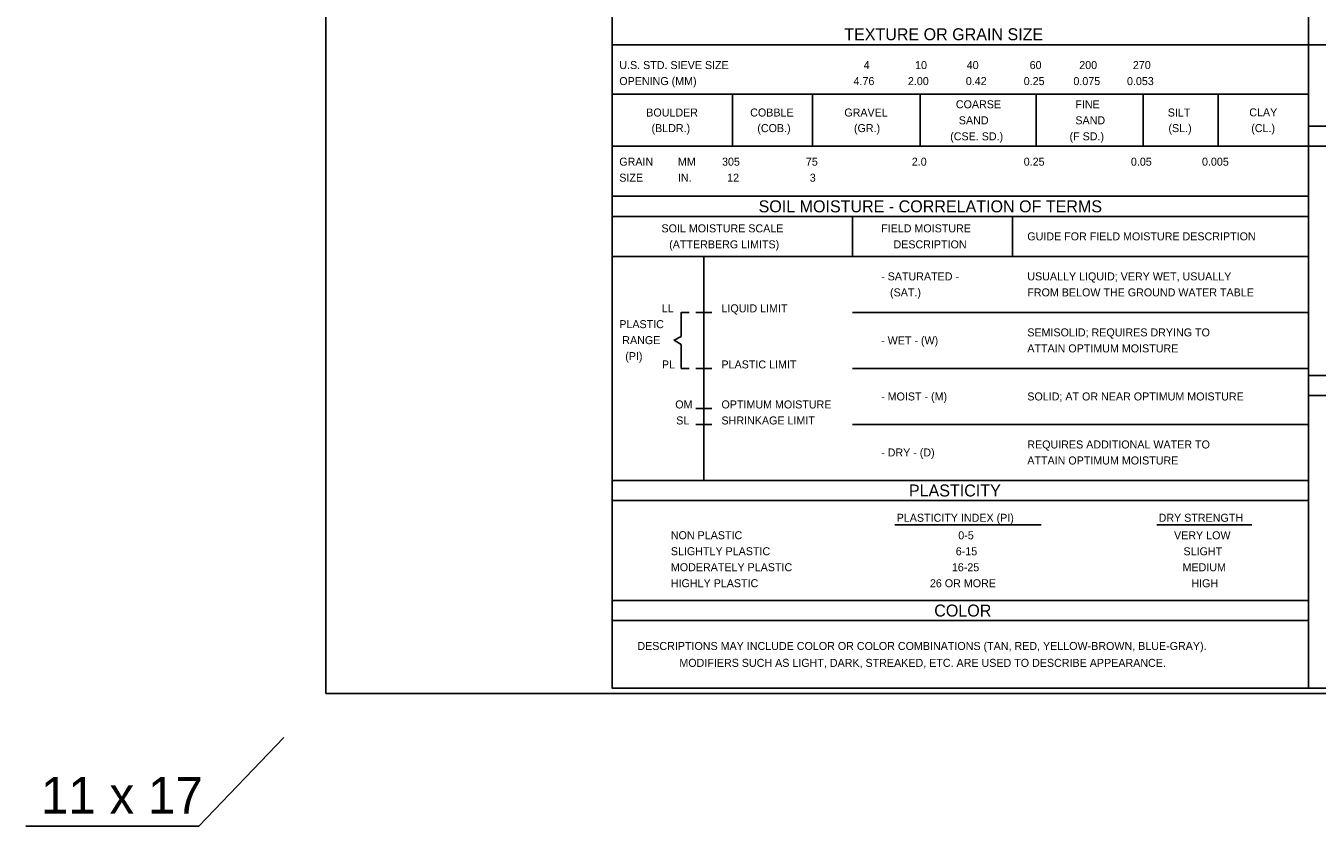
# Model space of a CAD drawing. Extents: x 278618 to 280654, y 171155 to 171855.
# Drawn here: x 280442.4 to 280512.3, y 171534 to 171577.4 of the extents above; entities that cross this region are included whole.
import ezdxf

# ---------------------------------------------------------------- set-up
doc = ezdxf.new("R2010")
doc.units = 0
for name, color, linetype in [('Geotech Sheets and Borders Cell', 7, 'Continuous'), ('Scratch_Level_0', 7, 'Continuous'), ('Sheet Plot Border Inside CELL', 7, 'Continuous')]:
    doc.layers.add(name, color=color, linetype=linetype)

msp = doc.modelspace()

# ---------------------------------------------------------------- linework, layer by layer
at = {"layer": 'Geotech Sheets and Borders Cell'}
for p, q in [((280511.888, 171621.702), (280511.888, 171541.488)), ((280474.148, 171576.353), (280549.148, 171576.353)), ((280474.148, 171573.68), (280511.888, 171573.68)), ((280480.655, 171573.68), (280480.655, 171570.86)), ((280484.993, 171573.68), (280484.993, 171570.86)), ((280490.84, 171573.68), (280490.84, 171570.86)), ((280497.117, 171573.68), (280497.117, 171570.86)), ((280502.926, 171573.68), (280502.926, 171570.86)), ((280506.991, 171573.68), (280506.991, 171570.86)), ((280511.888, 171571.945), (280549.148, 171571.945)), ((280474.148, 171570.86), (280511.888, 171570.86)), ((280511.888, 171570.86), (280549.148, 171570.86)), ((280474.148, 171568.15), (280511.888, 171568.15)), ((280474.148, 171567.065), (280511.888, 171567.065)), ((280487.162, 171567.065), (280487.162, 171564.896)), ((280495.838, 171567.065), (280495.838, 171564.896)), ((280474.148, 171564.896), (280511.888, 171564.896)), ((280479.105, 171564.896), (280479.105, 171552.75)), ((280479.539, 171561.86), (280478.672, 171561.86)), ((280479.105, 171561.86), (280479.539, 171561.86)), ((280487.162, 171561.86), (280511.888, 171561.86)), ((280479.539, 171558.823), (280478.672, 171558.823)), ((280487.162, 171558.823), (280511.888, 171558.823)), ((280511.888, 171558.44), (280549.148, 171558.44)), ((280511.888, 171557.355), (280549.148, 171557.355)), ((280479.539, 171556.654), (280478.672, 171556.654)), ((280479.539, 171555.786), (280478.672, 171555.786)), ((280487.162, 171555.786), (280511.888, 171555.786)), ((280474.148, 171552.75), (280511.888, 171552.75)), ((280474.148, 171551.665), (280511.888, 171551.665)), ((280489.467, 171550.354), (280497.396, 171550.354)), ((280503.663, 171550.354), (280508.807, 171550.354)), ((280474.148, 171546.243), (280511.888, 171546.243)), ((280474.148, 171545.158), (280511.888, 171545.158))]:
    msp.add_line(p, q, dxfattribs=at)
msp.add_lwpolyline([(280474.148, 171646.488), (280624.148, 171646.488), (280624.148, 171541.488), (280474.148, 171541.488)], close=True, dxfattribs=at)
for points in [[(280478.32, 171561.86), (280477.886, 171561.86), (280477.886, 171560.559)], [(280477.886, 171560.559), (280477.496, 171560.355), (280477.886, 171560.112)], [(280478.32, 171558.823), (280477.886, 171558.823), (280477.886, 171560.112)]]:
    msp.add_lwpolyline(points, dxfattribs=at)
at = {"layer": 'Scratch_Level_0'}
msp.add_line((280458.631, 171541.204), (280458.631, 171541.204), dxfattribs=at)
msp.add_lwpolyline([(280442.366, 171534.014), (280451.749, 171534.014), (280456.341, 171538.812)], dxfattribs=at)
at = {"layer": 'Sheet Plot Border Inside CELL'}
msp.add_lwpolyline([(280458.631, 171541.204), (280625.398, 171541.204), (280625.398, 171646.771), (280458.631, 171646.771)], close=True, dxfattribs=at)

# ---------------------------------------------------------------- texts
at = {"layer": 'Geotech Sheets and Borders Cell'}
for s, height, p in [('TEXTURE OR GRAIN SIZE', 0.6507, (280486.719, 171576.608)), ('U.S. STD. SIEVE SIZE', 0.43381, (280474.529, 171575.047)), ('4', 0.434, (280487.775, 171575.047)), ('10', 0.4338, (280490.558, 171575.047)), (' 40 ', 0.4338, (280493.197, 171575.047)), ('60', 0.4338, (280496.767, 171575.047)), ('200', 0.4338, (280499.456, 171575.047)), ('270', 0.4338, (280502.361, 171575.047)), ('OPENING (MM)', 0.43381, (280474.529, 171574.179)), ('4.76   ', 0.4338, (280487.222, 171574.179)), ('2.00', 0.4338, (280490.169, 171574.179)), ('0.42', 0.4338, (280493.307, 171574.179)), ('0.25', 0.4338, (280496.446, 171574.179)), ('0.075', 0.4338, (280499.139, 171574.179)), ('0.053', 0.4338, (280502.043, 171574.179)), ('COARSE', 0.4338, (280492.768, 171572.921)), ('FINE', 0.4338, (280499.245, 171572.921)), ('BOULDER', 0.4338, (280475.989, 171572.476)), ('COBBLE', 0.4338, (280481.623, 171572.476)), ('GRAVEL', 0.4338, (280486.723, 171572.476)), (' SAND', 0.4338, (280492.768, 171572.053)), ('SAND', 0.4338, (280499.245, 171572.053)), ('SILT', 0.4338, (280504.252, 171572.476)), ('CLAY', 0.4338, (280508.67, 171572.483)), ('(BLDR.)', 0.4338, (280476.275, 171571.63)), ('(COB.)', 0.4338, (280482.009, 171571.63)), ('(GR.)', 0.4338, (280487.247, 171571.63)), ('(SL.)', 0.4338, (280504.289, 171571.63)), ('(CL.)', 0.4338, (280508.777, 171571.63)), ('(CSE. SD.)', 0.4338, (280492.462, 171571.185)), ('(F SD.)', 0.4338, (280498.929, 171571.185)), ('GRAIN', 0.4338, (280474.529, 171569.811)), ('MM', 0.4338, (280477.704, 171569.811)), ('305', 0.4338, (280480.097, 171569.811)), ('75', 0.4338, (280484.64, 171569.811)), ('2.0', 0.4338, (280490.381, 171569.811)), ('0.25', 0.4338, (280496.446, 171569.811)), ('0.05', 0.4338, (280502.255, 171569.811)), ('0.005', 0.4338, (280506.108, 171569.811)), ('SIZE', 0.4338, (280474.529, 171568.943)), ('IN.', 0.4338, (280477.704, 171568.944)), ('12', 0.4338, (280480.373, 171568.944)), ('3', 0.434, (280484.851, 171568.944)), ('SOIL MOISTURE - CORRELATION OF TERMS', 0.6507, (280482.077, 171567.282)), ('SOIL MOISTURE SCALE', 0.43381, (280476.814, 171566.197)), ('FIELD MOISTURE', 0.43381, (280488.718, 171566.197)), ('GUIDE FOR FIELD MOISTURE DESCRIPTION', 0.43381, (280496.64, 171565.763)), ('(ATTERBERG LIMITS)', 0.43381, (280477.233, 171565.33)), ('DESCRIPTION', 0.43381, (280489.387, 171565.33)), ('- SATURATED -', 0.43381, (280488.718, 171563.594)), ('USUALLY LIQUID; VERY WET, USUALLY', 0.43381, (280496.64, 171563.594)), ('   (SAT.)', 0.4338, (280488.718, 171562.727)), ('FROM BELOW THE GROUND WATER TABLE', 0.43381, (280496.64, 171562.727)), ('LL', 0.4338, (280476.827, 171561.86)), ('LIQUID LIMIT', 0.43381, (280480.066, 171561.86)), ('PLASTIC', 0.4338, (280474.529, 171561.006)), (' RANGE', 0.4338, (280474.529, 171560.138)), ('- WET - (W)', 0.43381, (280488.718, 171560.124)), ('SEMISOLID; REQUIRES DRYING TO', 0.43381, (280496.64, 171560.558)), ('ATTAIN OPTIMUM MOISTURE', 0.43381, (280496.64, 171559.691)), ('  (PI)', 0.4338, (280474.529, 171559.271)), ('PL', 0.4338, (280476.841, 171558.823)), ('PLASTIC LIMIT', 0.43381, (280480.066, 171558.823)), ('OM', 0.4338, (280477.562, 171556.654)), ('OPTIMUM MOISTURE', 0.43381, (280480.066, 171556.654)), ('- MOIST - (M)', 0.43381, (280488.718, 171557.087)), ('SOLID; AT OR NEAR OPTIMUM MOISTURE', 0.43381, (280496.64, 171557.087)), ('SL', 0.4338, (280477.613, 171555.786)), ('SHRINKAGE LIMIT', 0.43381, (280480.066, 171555.786)), ('- DRY - (D)', 0.43381, (280488.718, 171554.051)), ('REQUIRES ADDITIONAL WATER TO', 0.43381, (280496.64, 171554.485)), ('ATTAIN OPTIMUM MOISTURE', 0.43381, (280496.64, 171553.617)), ('PLASTICITY', 0.6507, (280490.224, 171551.882)), ('PLASTICITY INDEX (PI)', 0.43381, (280489.561, 171550.512)), ('DRY STRENGTH', 0.43381, (280503.757, 171550.512)), ('NON PLASTIC', 0.43381, (280477.323, 171549.565)), ('0-5', 0.4338, (280492.9, 171549.562)), ('VERY LOW', 0.4338, (280504.592, 171549.562)), ('SLIGHTLY PLASTIC', 0.43381, (280477.323, 171548.698)), ('6-15', 0.4338, (280492.764, 171548.695)), ('SLIGHT', 0.4338, (280505.104, 171548.695)), ('MODERATELY PLASTIC', 0.43381, (280477.323, 171547.831)), ('16-25', 0.4338, (280492.552, 171547.828)), ('MEDIUM', 0.4338, (280505.053, 171547.828)), ('HIGHLY PLASTIC', 0.43381, (280477.323, 171546.964)), ('26 OR MORE', 0.4338, (280491.363, 171546.962)), ('HIGH', 0.4338, (280505.53, 171546.962)), ('COLOR', 0.6507, (280491.597, 171545.375)), ('DESCRIPTIONS MAY INCLUDE COLOR OR COLOR COMBINATIONS (TAN, RED, YELLOW-BROWN, BLUE-GRAY).', 0.43381, (280475.509, 171543.563)), ('MODIFIERS SUCH AS LIGHT, DARK, STREAKED, ETC. ARE USED TO DESCRIBE APPEARANCE.', 0.43381, (280477.784, 171542.648))]:
    msp.add_text(s, height=height, dxfattribs=at).set_placement(p)
at = {"layer": 'Scratch_Level_0'}
msp.add_text('11 x 17', height=2, dxfattribs=at).set_placement((280443.184, 171534.684))

doc.saveas('drawing.dxf')
